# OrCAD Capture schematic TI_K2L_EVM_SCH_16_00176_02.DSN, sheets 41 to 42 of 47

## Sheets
41 PAGE27 : K2L_NAND FLASH&EEPROM: size C; title: K2L EMIF, VDD and VSSMON, EMIFWAIT1 bfr, NAND Flash, I2C EEPROM
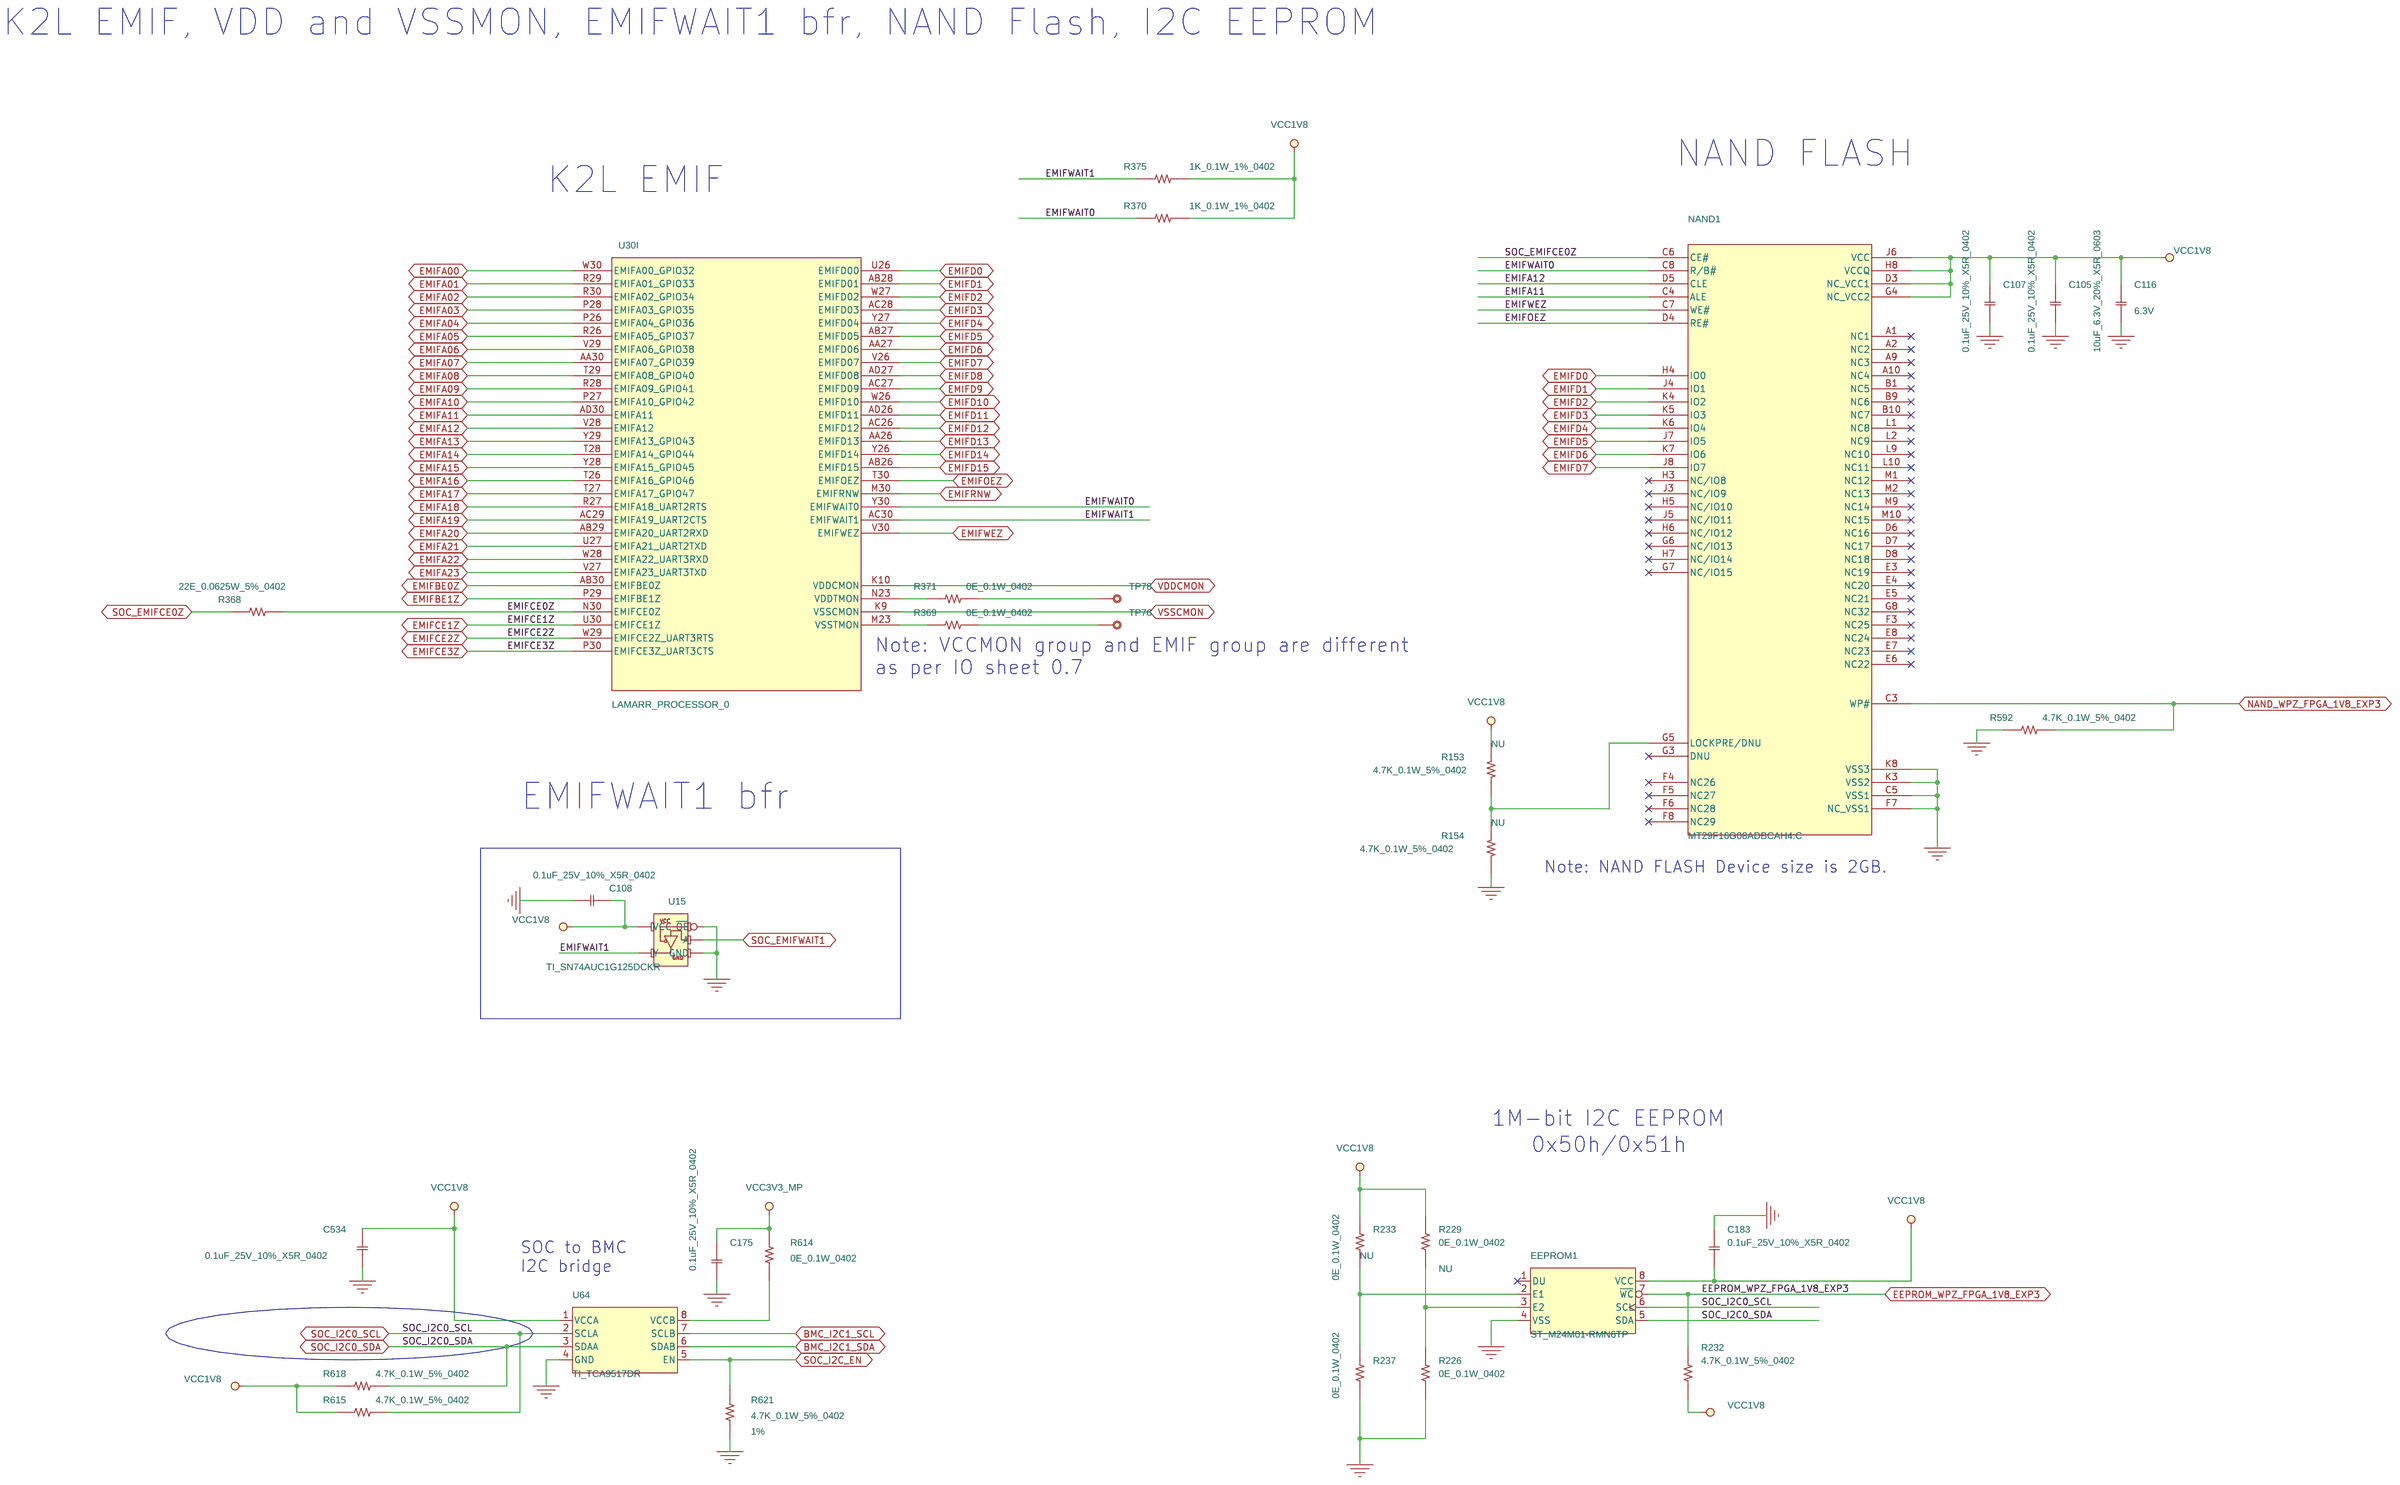
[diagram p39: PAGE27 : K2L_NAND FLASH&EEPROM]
42 PAGE41 : K2L_XDS200_EMULATION: size C; title: XDS200 Emulation CPLD
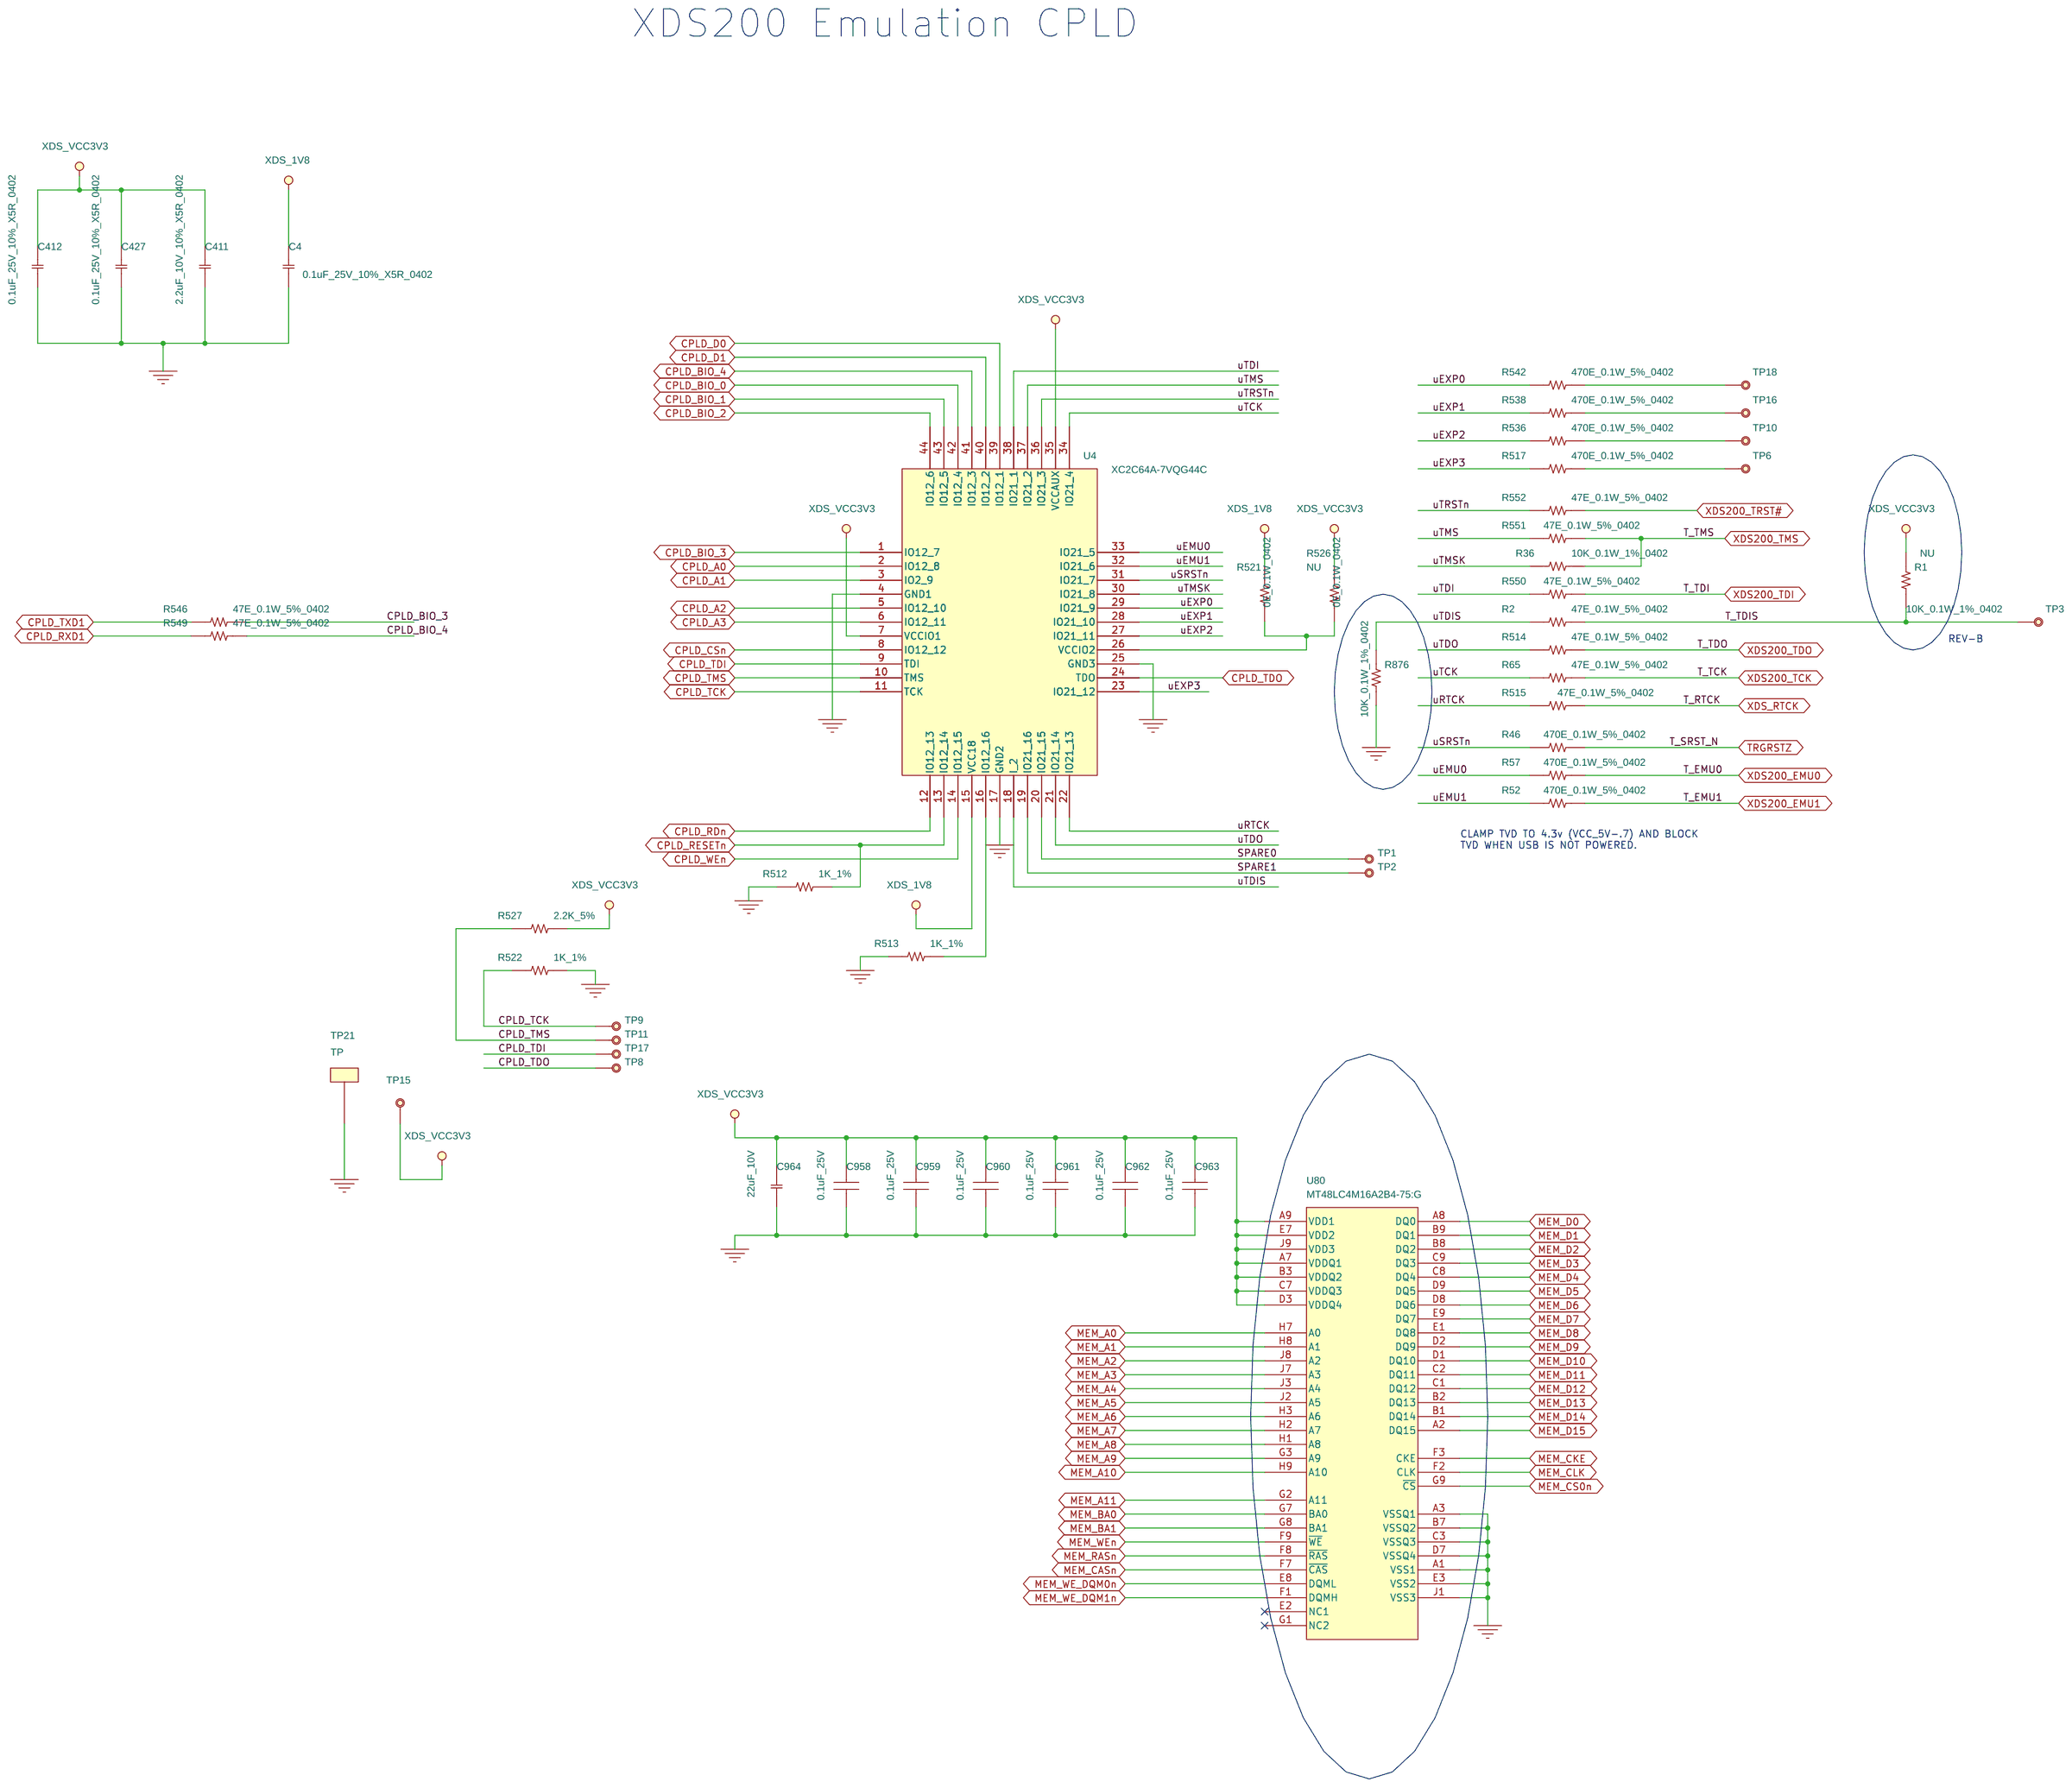
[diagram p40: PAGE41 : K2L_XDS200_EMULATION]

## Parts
sheet PAGE24 : K2L_JTAG
U30  LAMARR_PROCESSOR_0  [SKTBGA_Z3566_SS900-RHFB-BGA080]  (sections A,B,C,D,E,F,G,H,I,J,K,L,M,N,O,P,Q,R,S,T,U)
sheet PAGE27 : K2L_NAND FLASH&EEPROM
C105  0.1uF_25V_10%_X5R_0402  [C0402]
C107  0.1uF_25V_10%_X5R_0402  [C0402]
C108  0.1uF_25V_10%_X5R_0402  [C0402]
C116  10uF_6.3V_20%_X5R_0603  [C0603]
C175  0.1uF_25V_10%_X5R_0402  [C0402]
C183  0.1uF_25V_10%_X5R_0402  [C0402]
C534  0.1uF_25V_10%_X5R_0402  [C0402]
EEPROM1  ST_M24M01-RMN6TP  [SOIC_8P_50_193x236]
NAND1  MT29F16G08ADBCAH4:C  [BGA63C80P10X12_900X1100X100]
R153  4.7K_0.1W_5%_0402  [R0402]
R154  4.7K_0.1W_5%_0402  [R0402]
R226  0E_0.1W_0402  [R0402]
R229  0E_0.1W_0402  [R0402]
R232  4.7K_0.1W_5%_0402  [R0402]
R233  0E_0.1W_0402  [R0402]
R237  0E_0.1W_0402  [R0402]
R368  22E_0.0625W_5%_0402  [R0402]
R369  0E_0.1W_0402  [R0402]
R370  1K_0.1W_1%_0402  [R0402]
R371  0E_0.1W_0402  [R0402]
R375  1K_0.1W_1%_0402  [R0402]
R592  4.7K_0.1W_5%_0402  [R0402]
R614  0E_0.1W_0402  [R0402]
R615  4.7K_0.1W_5%_0402  [R0402]
R618  4.7K_0.1W_5%_0402  [R0402]
R621  4.7K_0.1W_5%_0402  [R0402]
TP76  TP  [TP-S40]
TP78  TP  [TP-S40]
U15  TI_SN74AUC1G125DCKR  [SC70_5P]
U64  TI_TCA9517DR  [SOIC_8P_50_193X236]
sheet PAGE41 : K2L_XDS200_EMULATION
C4  0.1uF_25V_10%_X5R_0402  [C0402]
C411  2.2uF_10V_10%_X5R_0402  [C0402]
C412  0.1uF_25V_10%_X5R_0402  [C0402]
C427  0.1uF_25V_10%_X5R_0402  [C0402]
C958  0.1uF_25V  [C0402]
C959  0.1uF_25V  [C0402]
C960  0.1uF_25V  [C0402]
C961  0.1uF_25V  [C0402]
C962  0.1uF_25V  [C0402]
C963  0.1uF_25V  [C0402]
C964  22uF_10V  [C0805]
R1  10K_0.1W_1%_0402  [R0402]
R2  47E_0.1W_5%_0402  [R0402]
R36  10K_0.1W_1%_0402  [R0402]
R46  470E_0.1W_5%_0402  [R0402]
R52  470E_0.1W_5%_0402  [R0402]
R57  470E_0.1W_5%_0402  [R0402]
R65  47E_0.1W_5%_0402  [R0402]
R512  1K_1%  [R0402]
R513  1K_1%  [R0402]
R514  47E_0.1W_5%_0402  [R0402]
R515  47E_0.1W_5%_0402  [R0402]
R517  470E_0.1W_5%_0402  [R0402]
R521  0E_0.1W_0402  [R0402]
R522  1K_1%  [R0402]
R526  0E_0.1W_0402  [R0402]
R527  2.2K_5%  [R0402]
R536  470E_0.1W_5%_0402  [R0402]
R538  470E_0.1W_5%_0402  [R0402]
R542  470E_0.1W_5%_0402  [R0402]
R546  47E_0.1W_5%_0402  [R0402]
R549  47E_0.1W_5%_0402  [R0402]
R550  47E_0.1W_5%_0402  [R0402]
R551  47E_0.1W_5%_0402  [R0402]
R552  47E_0.1W_5%_0402  [R0402]
R876  10K_0.1W_1%_0402  [R0402]
TP1  TP  [TP-S40]
TP2  TP  [TP-S40]
TP3  TP  [TP-S40]
TP6  TP  [TP-S40]
TP8  TP  [TP-S40]
TP9  TP  [TP-S40]
TP10  TP  [TP-S40]
TP11  TP  [TP-S40]
TP15  TP  [TP-S40]
TP16  TP  [TP-S40]
TP17  TP  [TP-S40]
TP18  TP  [TP-S40]
TP21  TP  [tp1-6040]
U4  XC2C64A-7VQG44C  [tqfp44]
U80  MT48LC4M16A2B4-75:G  [VFBGA54C80P9X9_800X800X100_EINF]

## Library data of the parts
U30 = LAMARR_PROCESSOR_7: LAMARR-SoC 900BGA 4DSP + 2ARM; Color: Default; Distributor_name: TBD; Distributor_part_number: TBD; EIC Part#: TBD; Location X-Coordinate: 0; Location Y-Coordinate: 0; Manufacture: TI; Manufacture Part Number: TCI6630K2L; Manufacture(English): TI; Manufacture_Part_Number: TCI6630K2L; Manufacturer: TI; Manufacturer_Part_No: TCI6630K2L; Mfg: TI; Mfg Part#: TBD; Mfr_name: TI; Mfr_part_number: LAMARR-SoC; Price @ 1: TBD; Price @ 10K: TBD; Price @ 1K: TBD; Primitive: DEFAULT; SPLIT_INST: TRUE; SWAP_INFO: (S1+S2+S3+S4+S5+S6+S7+S8+S9+S10+S11+S12+S13+S14+S15+S16+S17+S18+S19+S20+S21); Vendor: TBD; Vendor_Part_No: TBD; eI Part#: TBD
C105 C107 C108 C175 C183 C534 = 11_C_0: CAP CER 0.1UF 25V 10% X5R 0402; Avalue_Part_Number: E1123510400H; Distributor_name: DIGIKEY; Distributor_part_number: 445-4964-1-ND; EIC Part#: 03_00470_02; MOUNTED: <MOUNTED>; Manufacture: TDK Corporation; Manufacture Part Number: C1005X5R1E104K050BC; Manufacture(English): TDK Corporation; Manufacture_Part_Number: GRM155R71C104KA88D; Manufacturer: TDK Corporation; Manufacturer_Part_No: C1005X5R1E104K050BC; Mfg: Murata Electronics North America; Mfg Part#: 03_00470_02; Mfr_name: TDK Corporation; Mfr_part_number: C1005X5R1E104K050BC; Package: 0402; Price @ 1: 0.10000; Price @ 1K: 0.00420; ProcessType: SMT; Tolerance: 10%; Vendor: DIGIKEY; Vendor Part#: 445-4964-1-ND; Vendor_Part_No: 445-4964-1-ND; eI Part#: 03_00470_02
C116 = 11_C_0: CAP CER 10UF 6.3V 20% X5R 0603; Avalue_Part_Number: E1121610610H; Characteristic: 6.3V; Distributor_name: DIGIKEY; Distributor_part_number: 587-3383-1-ND; EIC Part#: 03_00605_01; GROUP: CPU1; Manufacture: Taiyo Yuden; Manufacture Part Number: JMK107ABJ106MAHT; Manufacture(English): Taiyo Yuden; Manufacture_Part_Number: JMK107ABJ106MAHT; Manufacturer: Taiyo Yuden; Manufacturer_Part_No: JMK107ABJ106MAHT; Mfg: Taiyo Yuden; Mfg Part#: JMK107ABJ106MAHT; Mfr_name: Taiyo Yuden; Mfr_part_number: JMK107ABJ106MAHT; Package: 0603; Part_Number: 1100004184; Price @ 1: 0.32000; Price @ 10K: 0.06105; Price @ 1K: 0.07755; ProcessType: SMT; ROOM: CPU1; Tolerance: 20%; Vendor: DIGIKEY; Vendor Part#: 587-3383-1-ND; Vendor_Part_No: 587-3383-1-ND; eI Part#: 03_00605_01
EEPROM1 = 141_ST_M24M01-HRMN6TP_0: IC EEPROM 1MBIT 1MHZ 8SO; AVL_Part: AVL; Distributor_name: DIGIKEY; Distributor_part_number: 497-6351-1-ND; EIC Part#: 01_01143_01; Manufacture: STMicroelectronics; Manufacture Part Number: M24M01-RMN6TP; Manufacture(English): STMicroelectronics; Manufacture_Part_Number: M24M01-RMN6TP; Manufacturer: STMicroelectronics; Manufacturer_Part_No: M24M01-RMN6TP; Mfg: STMicroelectronics; Mfg Part#: 01_01143_01; Mfr_name: STMicroelectronics; Mfr_part_number: M24M01-RMN6TP; Package: SOIC8; Part_Number: 1410021294-11; Price @ 1: 3.17000; Price @ 10K: 1.46300; Price @ 1K: 1.58400; ProcessType: SMT; Vendor: DIGIKEY; Vendor_Part_No: 497-6351-1-ND; eI Part#: 01_01143_01
NAND1 = IC_NAND_63VFBGA_MICRONx16: IC FLASH 16G SLC VFBGA; Distributor_name: TBD; Distributor_part_number: TBD; EIC Part#: 01_01145_01; Manufacture: Micron; Manufacture(English): Micron; Manufacturer: Micron; Mfg Part#: 01_01145_01; Mfr_name: Micron; Vendor: TBD; Vendor_Part_No: TBD; eI Part#: 01_01145_01
R153 R154 = 10_R_0: RES 4.7K OHM 1/10W 5% 0402 SMD; Advansus_Part_Number: 10G212472004030; Avalue_Part_Number: E1050704720H; Characteristic: 5%; Distributor_name: DIGIKEY; Distributor_part_number: P4.7KJCT-ND; EIC Part#: 02_00023_01; MOUNTED: <MOUNTED>; Manufacture: Panasonic - ECG; Manufacture Part Number: ERJ-2GEJ472X; Manufacture(English): Panasonic - ECG; Manufacture_Part_Number: ERJ-2GEJ472X; Manufacturer: Panasonic - ECG; Manufacturer_Part_No: ERJ-2GEJ472X; Mfg: Panasonic Electronic Components; Mfg Part#: 02_00266_01; Mfr_name: Panasonic - ECG; Mfr_part_number: ERJ-2GEJ472X; Mounting Status: NU; Mounting_Status: NU; Package: 0402; Part_Number: 105A747014; Price @ 1: 0.10000; Price @ 10K: 0.00347; Price @ 1K: 0.00672; ProcessType: SMT; Tolerance: 5%; Vendor: DIGIKEY; Vendor_Part_No: P4.7KJCT-ND; eI Part#: 02_00023_01
R226 R237 R614 = 10_R_0: RES 0.0 OHM 1/10W JUMP 0402 SMD; Characteristic: 5%; Distributor_name: DIGIKEY; Distributor_part_number: P0.0JCT-ND; EIC Part#: 02_00019_01; MOUNTED: <MOUNTED>; Manufacture: Panasonic - ECG; Manufacture Part Number: ERJ-2GE0R00X; Manufacture(English): Panasonic - ECG; Manufacture_Part_Number: ERJ-2GE0R00X; Manufacturer: Panasonic - ECG; Manufacturer_Part_No: ERJ-2GE0R00X; Mfg: Panasonic Electronic Components; Mfg Part#: 02_00019_01; Mfr_name: Panasonic - ECG; Mfr_part_number: ERJ-2GE0R00X; Package: 0402; Part_Number: 105A700004; Price @ 1: 0.05000; Price @ 10K: 0.00248; Price @ 1K: 0.00480; ProcessType: SMT; Tolerance: 5%; Vendor: DIGIKEY; Vendor_Part_No: P0.0JCT-ND; eI Part#: 02_00019_01
R229 R233 = 10_R_0: RES 0.0 OHM 1/10W JUMP 0402 SMD; Characteristic: 5%; Distributor_name: DIGIKEY; Distributor_part_number: P0.0JCT-ND; EIC Part#: 02_00019_01; MOUNTED: NU; Manufacture: Panasonic - ECG; Manufacture Part Number: ERJ-2GE0R00X; Manufacture(English): Panasonic - ECG; Manufacture_Part_Number: ERJ-2GE0R00X; Manufacturer: Panasonic - ECG; Manufacturer_Part_No: ERJ-2GE0R00X; Mfg: Panasonic Electronic Components; Mfg Part#: 02_00019_01; Mfr_name: Panasonic - ECG; Mfr_part_number: ERJ-2GE0R00X; Mounting Status: NU; Mounting_Status: NU; Package: 0402; Part_Number: 105A700004; Price @ 1: 0.05000; Price @ 10K: 0.00248; Price @ 1K: 0.00480; ProcessType: SMT; Tolerance: 5%; Vendor: DIGIKEY; Vendor_Part_No: P0.0JCT-ND; eI Part#: 02_00019_01
R232 R592 = 10_R_0: RES 4.7K OHM 1/10W 5% 0402 SMD; Advansus_Part_Number: 10G212472004030; Avalue_Part_Number: E1050704720H; Characteristic: 5%; Distributor_name: DIGIKEY; Distributor_part_number: P4.7KJCT-ND; EIC Part#: 02_00023_01; MOUNTED: <MOUNTED>; Manufacture: Panasonic - ECG; Manufacture Part Number: ERJ-2GEJ472X; Manufacture(English): Panasonic - ECG; Manufacture_Part_Number: ERJ-2GEJ472X; Manufacturer: Panasonic - ECG; Manufacturer_Part_No: ERJ-2GEJ472X; Mfg: Panasonic Electronic Components; Mfg Part#: 02_00266_01; Mfr_name: Panasonic - ECG; Mfr_part_number: ERJ-2GEJ472X; Package: 0402; Part_Number: 105A747014; Price @ 1: 0.10000; Price @ 10K: 0.00347; Price @ 1K: 0.00672; ProcessType: SMT; Tolerance: 5%; Vendor: DIGIKEY; Vendor_Part_No: P4.7KJCT-ND; eI Part#: 02_00023_01
R368 = 10_R_0: RES 22 OHM 1/16W 1% 0402 SMD; Characteristic: 5%; Distributor_name: DIGIKEY; Distributor_part_number: P22JCT-ND; EIC Part#: 02_00233_01; MOUNTED: <MOUNTED>; Manufacture: Panasonic - ECG; Manufacture Part Number: ERJ-2GEJ220X; Manufacture(English): Panasonic - ECG; Manufacture_Part_Number: ERJ-2GEJ220X; Manufacturer: Panasonic - ECG; Manufacturer_Part_No: ERJ-2GEJ220X; Mfg: Panasonic - ECG; Mfg Part#: ERJ-2GEJ220X; Mfr_name: Panasonic - ECG; Mfr_part_number: ERJ-2GEJ220X; Package: 0402; Part_Number: 105A722064; Price @ 1: 0.10000; Price @ 10K: 0.00132; Price @ 1K: 0.00233; ProcessType: SMT; Tolerance: 5%; Vendor: DIGIKEY; Vendor Part#: P22JCT-ND; Vendor_Part_No: P22JCT-ND; eI Part#: 02_00233_01
R369 R371 = 10_R_0: RES 0.0 OHM 1/10W JUMP 0402 SMD; Characteristic: 5%; Distributor_name: DIGIKEY; Distributor_part_number: P0.0JCT-ND; EIC Part#: 02_00019_01; Manufacture: Panasonic - ECG; Manufacture Part Number: ERJ-2GE0R00X; Manufacture(English): Panasonic - ECG; Manufacture_Part_Number: ERJ-2GE0R00X; Manufacturer: Panasonic - ECG; Manufacturer_Part_No: ERJ-2GE0R00X; Mfg: Panasonic Electronic Components; Mfg Part#: 02_00019_01; Mfr_name: Panasonic - ECG; Mfr_part_number: ERJ-2GE0R00X; Package: 0402; Part_Number: 105A700004; Price @ 1: 0.05000; Price @ 10K: 0.00248; Price @ 1K: 0.00480; ProcessType: SMT; Tolerance: 5%; Vendor: DIGIKEY; Vendor_Part_No: P0.0JCT-ND; eI Part#: 02_00019_01
R370 R375 = 10_R_0: RES 1.00K OHM 1/10W 1% 0402 SMD; Characteristic: 1%; Distributor_name: DIGIKEY; Distributor_part_number: P1.00KLCT-ND; EIC Part#: 02_00045_01; MOUNTED: <MOUNTED>; Manufacture: Panasonic - ECG; Manufacture Part Number: ERJ-2RKF1001X; Manufacture(English): Panasonic - ECG; Manufacture_Part_Number: ERJ-2RKF1001X; Manufacturer: Panasonic - ECG; Manufacturer_Part_No: ERJ-2RKF1001X; Mfg: Panasonic Electronic Components; Mfg Part#: 02_00045_01; Mfr_name: Panasonic - ECG; Mfr_part_number: ERJ-2RKF1001X; Package: 0402; Part_Number: 105A510014; Price @ 1: 0.10000; Price @ 10K: 0.00347; Price @ 1K: 0.00672; ProcessType: SMT; Tolerance: 1%; Vendor: DIGIKEY; Vendor_Part_No: P1.00KLCT-ND; eI Part#: 02_00045_01
R615 R618 R621 = 10_R_0: RES 4.7K OHM 1/10W 5% 0402 SMD; AVL_Part: AVL; Advansus_Part_Number: 10G212470114030; Characteristic: 1%; Distributor_name: DIGIKEY; Distributor_part_number: P4.7KJCT-ND; EIC Part#: 02_00023_01; MOUNTED: <MOUNTED>; Manufacture: Panasonic - ECG; Manufacture Part Number: ERJ-2GEJ472X; Manufacture(English): Panasonic - ECG; Manufacture_Part_Number: ERJ-2GEJ472X; Manufacturer: Panasonic - ECG; Manufacturer_Part_No: ERJ-2GEJ472X; Mfg: Panasonic Electronic Components; Mfg Part#: 02_00266_01; Mfr_name: Panasonic - ECG; Mfr_part_number: ERJ-2GEJ472X; Package: 0402; Part_Number: 1000000558-04; Price @ 1: 0.10000; Price @ 10K: 0.00347; Price @ 1K: 0.00672; ProcessType: SMT; Tolerance: 1%; Vendor: DIGIKEY; Vendor_Part_No: P4.7KJCT-ND; eI Part#: 02_00023_01
TP76 TP78 = 00_TP28_0: TEST PAD TP; Advansus_Part_Number: 0030000003; Avalue_Part_Number: 0030000003; Distributor_name: NA; Distributor_part_number: NA; EIC Part#: NA; Manufacture: NA; Manufacture Part Number: NA; Manufacture(English): NA; Manufacture_Part_Number: NA; Manufacturer: NA; Manufacturer_Part_No: NA; Mfg: NA; Mfg Part#: NA; Mfr_name: NA; Mfr_part_number: NA; Part_Number: 0030000003; Price @ 1: NA; Price @ 10K: NA; Price @ 1K: NA; ProcessType: SMT; Vendor: NA; Vendor_Part_No: NA; eI Part#: NA
U15 = 141_TI_SN74AUC1G125DCKR_0: IC BUS BUFF TRI-ST N-INV SC705; AVL_Part: AVL; Advansus_Part_Number: 06GA1410009148; Distributor_name: DIGIKEY; Distributor_part_number: 296-12658-1-ND; EIC Part#: TBD; Manufacture: TI; Manufacture Part Number: SN74AUC1G125DCKR; Manufacture(English): TI; Manufacture_Part_Number: SN74AUC1G125DCKR; Manufacturer: TI; Manufacturer_Part_No: SN74AUC1G125DCKR; Mfg: TI; Mfg Part#: TBD; Mfr_name: TI; Mfr_part_number: SN74AUC1G125DCKR; Package: SC70-5; Part_Number: 1410009148; Price @ 1: 0.57000; Price @ 10K: 0.10440; Price @ 1K: 0.11948; ProcessType: SMT; Tolerance: NA; Vendor: DIGIKEY; Vendor_Part_No: 296-12658-1-ND; eI Part#: 01_00039_01
U64 = 141_TI_PCA9517DR_0: IC LVL-TRANSL I2C BUS REP 8-SOIC; AVL_Part: AVL; Alternate_Mfr: TI; Alternate_Partno: TCA9517DR; Distributor_name: DIGIKEY; Distributor_part_number: 296-23734-1-ND; EIC Part#: TBD; Manufacture: TI; Manufacture Part Number: PCA9517DR; Manufacture(English): TI; Manufacture_Part_Number: PCA9517DR; Manufacturer: TI; Manufacturer_Part_No: PCA9517DR; Mfg: TI; Mfg Part#: TBD; Mfr_name: TI; Mfr_part_number: PCA9517DR; Package: SOIC8; Part_Number: 1410015122; Price @ 1: 2.94000; Price @ 10K: 1.35660; Price @ 1K: 1.46880; ProcessType: SMT; Vendor: DIGIKEY; Vendor_Part_No: 296-23734-1-ND; eI Part#: 01_00472_01
C4 C412 C427 = 11_C_0: CAP CER 0.1UF 25V 10% X5R 0402; Alt Mfg: Taiyo Yuden; Distributor_name: DIGIKEY; Distributor_part_number: 445-4964-1-ND; EIC Part#: 03_00470_02; Manufacture: TDK Corporation; Manufacture Part Number: C1005X5R1E104K050BC; Manufacture(English): TDK Corporation; Manufacture_Part_Number: GRM155R61E104KA87D; Manufacturer: TDK Corporation; Manufacturer_Part_No: C1005X5R1E104K050BC; Mfg: Murata Electronics North America; Mfg Part#: 03_00470_02; Mfr_name: TDK Corporation; Mfr_part_number: C1005X5R1E104K050BC; Oper. Temp. Range: -55°C ~ 85°C; Package: 0402; Price @ 1: 0.10000; Price @ 1K: 0.00960; ProcessType: SMT; RoHS: Yes; Tolerance: 10%; Vendor: DIGIKEY; Vendor Part#: 445-4964-1-ND; Vendor_Part_No: 445-4964-1-ND; eI Part#: 03_00470_02
C411 = 11_C_0: CAP CER 2.2UF 10V 10% X5R 0402; AVL_Part: AVL; Advansus_Part_Number: 11G233222516360; Characteristic: 10V; Distributor_name: DIGIKEY; Distributor_part_number: 445-7392-1-ND; EIC Part#: 03_00055_05; Manufacture: TDK Corporation; Manufacture Part Number: C1005X5R1A225K050BC; Manufacture(English): TDK Corporation; Manufacture_Part_Number: C1005X5R1A225K050BC; Manufacturer: TDK Corporation; Manufacturer_Part_No: C1005X5R1A225K050BC; Mfg: TDK Corporation; Mfg Part#: C1005X5R1A225K050BC; Mfr_name: TDK Corporation; Mfr_part_number: C1005X5R1A225K050BC; Package: 0402; Part_Number: 1100007233-01; Price @ 1: 0.13000; Price @ 10K: 0.01935; Price @ 1K: 0.02475; ProcessType: SMT; Tolerance: 10%; Vendor: DIGIKEY; Vendor_Part_No: 445-7392-1-ND; eI Part#: 03_00055_05
C958-C963 = CAP: CAP CER 0.1UF 25V 10% X5R 0402; Distributor_name: DIGIKEY; Distributor_part_number: 445-4964-1-ND; EIC Part#: 03_00470_02; Manufacture: TDK Corporation; Manufacture Part Number: C1005X5R1E104K050BC; Manufacture(English): TDK Corporation; Manufacture_Part_Number: GRM155R61E104KA87D; Manufacturer: TDK Corporation; Manufacturer_Part_No: C1005X5R1E104K050BC; Mfg: Murata Electronics North America; Mfg Part#: 03_00470_02; Mfr_name: TDK Corporation; Mfr_part_number: C1005X5R1E104K050BC; Price @ 1: 0.10000; Price @ 1K: 0.00960; Vendor: DIGIKEY; Vendor Part#: 445-4964-1-ND; Vendor_Part_No: 445-4964-1-ND; eI Part#: 03_00470_02
C964 = 11_C_0: CAP CER 22UF 10V 20% X5R 0805; Characteristic: 6.3V; Distributor_name: DIGIKEY; Distributor_part_number: 587-1958-1-ND; EIC Part#: 03_00263_01; Manufacture: Taiyo Yuden; Manufacture Part Number: LMK212BJ226MG-T; Manufacture(English): Taiyo Yuden; Manufacture_Part_Number: LMK212BJ226MG-T; Manufacturer: Taiyo Yuden; Manufacturer_Part_No: LMK212BJ226MG-T; Mfg: Taiyo Yuden; Mfg Part#: 03_00263_01; Mfr_name: Taiyo Yuden; Mfr_part_number: LMK212BJ226MG-T; Package: 0805; Part_Number: 1100000254; Price @ 1: 0.53000; Price @ 10K: 0.12000; Price @ 1K: 0.16875; ProcessType: SMT; Tolerance: 20%; Vendor: DIGIKEY; Vendor Part#: 587-1958-1-ND; Vendor_Part_No: 587-1958-1-ND; eI Part#: 03_00263_01
R1 = 10_R_0: RES 10K OHM 1/10W 1% 0402 SMD; Alt Mfg: Yageo; Alt Mfg Part#: RC0402FR-0710KL; Distributor_name: DIGIKEY; Distributor_part_number: P10.0KLCT-ND; EIC Part#: 02_00027_01; Manufacture: Panasonic - ECG; Manufacture Part Number: ERJ-2RKF1002X; Manufacture(English): Panasonic - ECG; Manufacture_Part_Number: ERJ-2RKF1002X; Manufacturer: Panasonic - ECG; Manufacturer_Part_No: ERJ-2RKF1002X; Mfg Part#: 02_00027_01; Mfr_name: Panasonic - ECG; Mfr_part_number: ERJ-2RKF1002X; Mounting: NU; Mounting Status: NU; Mounting_Status: NU; Oper. Temp. Range: -55C ~ 125C; Package: 0402; Price @ 1: 0.10000; Price @ 10K: 0.00347; Price @ 1K: 0.00672; ProcessType: SMT; Remark: Alt part is 1/16W; RoHS: Yes; Tolerance: 1%; Vendor: DIGIKEY; Vendor Part#: P10.0KLCT-ND; Vendor_Part_No: P10.0KLCT-ND; eI Part#: 02_00027_01
R2 = 10_R_0: RES 47 OHM 1/10W 5% 0402 SMD; Alt Mfg: Yageo; Alt Mfg Part#: RC0402JR-070RL; Distributor_name: DIGIKEY; Distributor_part_number: P47JCT-ND; EIC Part#: 02_00558_01; Manufacture: Panasonic - ECG; Manufacture Part Number: ERJ-2GEJ470X; Manufacture(English): Panasonic - ECG; Manufacture_Part_Number: ERJ-2GEJ470X; Manufacturer: Panasonic - ECG; Manufacturer_Part_No: ERJ-2GEJ470X; Mfg Part#: 02_00558_01; Mfr_name: Panasonic - ECG; Mfr_part_number: ERJ-2GEJ470X; Oper. Temp. Range: -55C to 125C; Package: 0402; ProcessType: SMT; Remark: Alt part is 1/16W; RoHS: Yes; Tolerance: 5%; Vendor: DIGIKEY; Vendor Part#: P47JCT-ND; Vendor_Part_No: P47JCT-ND; eI Part#: 02_00043_02
R36 R876 = 10_R_0: RES 10K OHM 1/10W 1% 0402 SMD; Alt Mfg: Yageo; Alt Mfg Part#: RC0402FR-0710KL; Distributor_name: DIGIKEY; Distributor_part_number: P10.0KLCT-ND; EIC Part#: 02_00027_01; Manufacture: Panasonic - ECG; Manufacture Part Number: ERJ-2RKF1002X; Manufacture(English): Panasonic - ECG; Manufacture_Part_Number: ERJ-2RKF1002X; Manufacturer: Panasonic - ECG; Manufacturer_Part_No: ERJ-2RKF1002X; Mfg Part#: 02_00027_01; Mfr_name: Panasonic - ECG; Mfr_part_number: ERJ-2RKF1002X; Oper. Temp. Range: -55C ~ 125C; Package: 0402; Price @ 1: 0.10000; Price @ 10K: 0.00347; Price @ 1K: 0.00672; ProcessType: SMT; Remark: Alt part is 1/16W; RoHS: Yes; Tolerance: 1%; Vendor: DIGIKEY; Vendor Part#: P10.0KLCT-ND; Vendor_Part_No: P10.0KLCT-ND; eI Part#: 02_00027_01
R46 R57 = 10_R_0: RES 470 OHM 1/10W 5% 0402 SMD; Alt Mfg: Yageo; Alt Mfg Part#: RC0402JR-070RL; Distributor_name: DIGIKEY; Distributor_part_number: P470JCT-ND; EIC Part#: 02_00483_01; Manufacture: Panasonic - ECG; Manufacture Part Number: ERJ-2GEJ471X; Manufacture(English): Panasonic - ECG; Manufacture_Part_Number: ERJ-2GEJ471X; Manufacturer: Panasonic - ECG; Manufacturer_Part_No: ERJ-2GEJ471X; Mfg Part#: 02_00483_01; Mfr_name: Panasonic - ECG; Mfr_part_number: ERJ-2GEJ471X; Oper. Temp. Range: -55C to 125C; Package: 0402; ProcessType: SMT; Remark: Alt part is 1/16W; RoHS: Yes; Tolerance: 5%; Vendor: DIGIKEY; Vendor Part#: P470JDKR-ND; Vendor_Part_No: P470JCT-ND; eI Part#: 02_00972_01
R52 R542 = 10_R_0: RES 470 OHM 1/10W 5% 0402 SMD; Alt Mfg: Yageo; Alt Mfg Part#: RC0402JR-070RL; Distributor_name: DIGIKEY; Distributor_part_number: P470JCT-ND; EIC Part#: 02_00483_01; Manufacture: Panasonic - ECG; Manufacture Part Number: ERJ-2GEJ471X; Manufacture(English): Panasonic - ECG; Manufacture_Part_Number: ERJ-2GEJ471X; Manufacturer: Panasonic - ECG; Manufacturer_Part_No: ERJ-2GEJ471X; Mfg Part#: 02_00483_01; Mfr_name: Panasonic - ECG; Mfr_part_number: ERJ-2GEJ471X; Oper. Temp. Range: -55C to 125C; Package: 0402; ProcessType: SMT; Remark: Alt part is 1/16W; RoHS: Yes; Tolerance: 5%; Vendor: DIGIKEY; Vendor Part#: P470JDKR-ND; Vendor_Part_No: P470JCT-ND; eI Part#: TBD
R65 R515 R546 R550 = 10_R_0: RES 47 OHM 1/10W 5% 0402 SMD; Alt Mfg: Yageo; Alt Mfg Part#: RC0402JR-070RL; Distributor_name: DIGIKEY; Distributor_part_number: P47JCT-ND; EIC Part#: 02_00558_01; Manufacture: Panasonic - ECG; Manufacture Part Number: ERJ-2GEJ470X; Manufacture(English): Panasonic - ECG; Manufacture_Part_Number: ERJ-2GEJ470X; Manufacturer: Panasonic - ECG; Manufacturer_Part_No: ERJ-2GEJ470X; Mfg Part#: 02_00558_01; Mfr_name: Panasonic - ECG; Mfr_part_number: ERJ-2GEJ470X; Oper. Temp. Range: -55C to 125C; Package: 0402; ProcessType: SMT; Remark: Alt part is 1/16W; RoHS: Yes; Tolerance: 5%; Vendor: DIGIKEY; Vendor Part#: P47JCT-ND; Vendor_Part_No: P47JCT-ND; eI Part#: 02_00019_01
R512 R513 R522 = 10_R_0: RES 1.00K OHM 1/10W 1% 0402 SMD; Alt Mfg: Yageo; Distributor_name: DIGIKEY; Distributor_part_number: P1.00KLCT-ND; EIC Part#: 02_00045_01; MOUNTED: <MOUNTED>; Manufacture: Panasonic - ECG; Manufacture Part Number: ERJ-2RKF1001X; Manufacture(English): Panasonic - ECG; Manufacture_Part_Number: ERJ-2RKF1001X; Manufacturer: Panasonic - ECG; Manufacturer_Part_No: ERJ-2RKF1001X; Mfg Part#: 02_00045_01; Mfr_name: Panasonic - ECG; Mfr_part_number: ERJ-2RKF1001X; Oper. Temp. Range: -55C to 125C; Package: 0402; ProcessType: SMT; RoHS: Yes; Tolerance: 1%; Vendor: DIGIKEY; Vendor Part#: P1.00KLCT-ND; Vendor_Part_No: P1.00KLCT-ND; eI Part#: 02_00045_01
R514 R549 = 10_R_0: RES 47 OHM 1/10W 5% 0402 SMD; Alt Mfg: Yageo; Alt Mfg Part#: RC0402JR-070RL; Distributor_name: DIGIKEY; Distributor_part_number: P47JCT-ND; EIC Part#: 02_00558_01; Manufacture: Panasonic - ECG; Manufacture Part Number: ERJ-2GEJ470X; Manufacture(English): Panasonic - ECG; Manufacture_Part_Number: ERJ-2GEJ470X; Manufacturer: Panasonic - ECG; Manufacturer_Part_No: ERJ-2GEJ470X; Mfg Part#: 02_00558_01; Mfr_name: Panasonic - ECG; Mfr_part_number: ERJ-2GEJ470X; Oper. Temp. Range: -55C to 125C; Package: 0402; ProcessType: SMT; Remark: Alt part is 1/16W; RoHS: Yes; Tolerance: 5%; Vendor: DIGIKEY; Vendor Part#: P47JCT-ND; Vendor_Part_No: P47JCT-ND; eI Part#: 02_00233_01
R517 = 10_R_0: RES 470 OHM 1/10W 5% 0402 SMD; Alt Mfg: Yageo; Alt Mfg Part#: RC0402JR-070RL; Distributor_name: DIGIKEY; Distributor_part_number: P470JCT-ND; EIC Part#: 02_00483_01; Manufacture: Panasonic - ECG; Manufacture Part Number: ERJ-2GEJ471X; Manufacture(English): Panasonic - ECG; Manufacture_Part_Number: ERJ-2GEJ471X; Manufacturer: Panasonic - ECG; Manufacturer_Part_No: ERJ-2GEJ471X; Mfg Part#: 02_00483_01; Mfr_name: Panasonic - ECG; Mfr_part_number: ERJ-2GEJ471X; Oper. Temp. Range: -55C to 125C; Package: 0402; ProcessType: SMT; Remark: Alt part is 1/16W; RoHS: Yes; Tolerance: 5%; Vendor: DIGIKEY; Vendor Part#: P470JDKR-ND; Vendor_Part_No: P470JCT-ND; eI Part#: 02_00027_01
R521 = 10_R_0: RES 0.0 OHM 1/10W JUMP 0402 SMD; Alt Mfg: Yageo; Distributor_name: DIGIKEY; Distributor_part_number: P0.0JCT-ND; EIC Part#: 02_00019_01; Manufacture: Panasonic - ECG; Manufacture Part Number: ERJ-2GE0R00X; Manufacture(English): Panasonic - ECG; Manufacture_Part_Number: ERJ-2GE0R00X; Manufacturer: Panasonic - ECG; Manufacturer_Part_No: ERJ-2GE0R00X; Mfg Part#: 02_00019_01; Mfr_name: Panasonic - ECG; Mfr_part_number: ERJ-2GE0R00X; Oper. Temp. Range: -55C to 125C; Package: 0402; ProcessType: SMT; Remark: Alt part is 1/16W; RoHS: Yes; Tolerance: 5%; Vendor: DIGIKEY; Vendor Part#: P0.0JCT-ND; Vendor_Part_No: P0.0JCT-ND; eI Part#: 02_00019_01
R526 = 10_R_0: RES 0.0 OHM 1/10W JUMP 0402 SMD; Alt Mfg: Yageo; Distributor_name: DIGIKEY; Distributor_part_number: P0.0JCT-ND; EIC Part#: 02_00019_01; Manufacture: Panasonic - ECG; Manufacture Part Number: ERJ-2GE0R00X; Manufacture(English): Panasonic - ECG; Manufacture_Part_Number: ERJ-2GE0R00X; Manufacturer: Panasonic - ECG; Manufacturer_Part_No: ERJ-2GE0R00X; Mfg Part#: 02_00019_01; Mfr_name: Panasonic - ECG; Mfr_part_number: ERJ-2GE0R00X; Mounting: NU; Mounting Status: NU; Mounting_Status: NU; Oper. Temp. Range: -55C to 125C; Package: 0402; ProcessType: SMT; Remark: Alt part is 1/16W; RoHS: Yes; Tolerance: 5%; Vendor: DIGIKEY; Vendor Part#: P0.0JCT-ND; Vendor_Part_No: P0.0JCT-ND; eI Part#: 02_00019_01
R527 = 10_R_0: RES 2.2K OHM 1/10W 5% 0402 SMD; Alt Mfg: Yageo; Alt Mfg Part#: RC0402JR-072K2L; Distributor_name: DIGIKEY; Distributor_part_number: P2.2KJCT-ND; EIC Part#: 02_00024_01; Manufacture: Panasonic - ECG; Manufacture Part Number: ERJ-2GEJ222X; Manufacture(English): Panasonic - ECG; Manufacture_Part_Number: ERJ-2GEJ222X; Manufacturer: Panasonic - ECG; Manufacturer_Part_No: ERJ-2GEJ222X; Mfg Part#: 02_00024_01; Mfr_name: Panasonic - ECG; Mfr_part_number: ERJ-2GEJ222X; Oper. Temp. Range: -55C to 125C; Package: 0402; ProcessType: SMT; Remark: Alt part is 1/16W; RoHS: Yes; Specifications: RES 2.2K OHM 1/10W 5% 0402 SMD; Tolerance: 5%; Vendor: DIGIKEY; Vendor Part#: P2.2KJCT-ND; Vendor_Part_No: P2.2KJCT-ND; eI Part#: 09_00060_01
R536 = 10_R_0: RES 470 OHM 1/10W 5% 0402 SMD; Alt Mfg: Yageo; Alt Mfg Part#: RC0402JR-070RL; Distributor_name: DIGIKEY; Distributor_part_number: P470JCT-ND; EIC Part#: 02_00483_01; Manufacture: Panasonic - ECG; Manufacture Part Number: ERJ-2GEJ471X; Manufacture(English): Panasonic - ECG; Manufacture_Part_Number: ERJ-2GEJ471X; Manufacturer: Panasonic - ECG; Manufacturer_Part_No: ERJ-2GEJ471X; Mfg Part#: 02_00483_01; Mfr_name: Panasonic - ECG; Mfr_part_number: ERJ-2GEJ471X; Oper. Temp. Range: -55C to 125C; Package: 0402; ProcessType: SMT; Remark: Alt part is 1/16W; RoHS: Yes; Tolerance: 5%; Vendor: DIGIKEY; Vendor Part#: P470JDKR-ND; Vendor_Part_No: P470JCT-ND; eI Part#: 02_00200_04
R538 = 10_R_0: RES 470 OHM 1/10W 5% 0402 SMD; Alt Mfg: Yageo; Alt Mfg Part#: RC0402JR-070RL; Distributor_name: DIGIKEY; Distributor_part_number: P470JCT-ND; EIC Part#: 02_00483_01; Manufacture: Panasonic - ECG; Manufacture Part Number: ERJ-2GEJ471X; Manufacture(English): Panasonic - ECG; Manufacture_Part_Number: ERJ-2GEJ471X; Manufacturer: Panasonic - ECG; Manufacturer_Part_No: ERJ-2GEJ471X; Mfg Part#: 02_00483_01; Mfr_name: Panasonic - ECG; Mfr_part_number: ERJ-2GEJ471X; Oper. Temp. Range: -55C to 125C; Package: 0402; ProcessType: SMT; Remark: Alt part is 1/16W; RoHS: Yes; Tolerance: 5%; Vendor: DIGIKEY; Vendor Part#: P470JDKR-ND; Vendor_Part_No: P470JCT-ND; eI Part#: 02_00961_01
R551 = 10_R_0: RES 47 OHM 1/10W 5% 0402 SMD; Alt Mfg: Yageo; Alt Mfg Part#: RC0402JR-070RL; Distributor_name: DIGIKEY; Distributor_part_number: P47JCT-ND; EIC Part#: 02_00558_01; Manufacture: Panasonic - ECG; Manufacture Part Number: ERJ-2GEJ470X; Manufacture(English): Panasonic - ECG; Manufacture_Part_Number: ERJ-2GEJ470X; Manufacturer: Panasonic - ECG; Manufacturer_Part_No: ERJ-2GEJ470X; Mfg Part#: 02_00558_01; Mfr_name: Panasonic - ECG; Mfr_part_number: ERJ-2GEJ470X; Oper. Temp. Range: -55C to 125C; Package: 0402; ProcessType: SMT; Remark: Alt part is 1/16W; RoHS: Yes; Tolerance: 5%; Vendor: DIGIKEY; Vendor Part#: P47JCT-ND; Vendor_Part_No: P47JCT-ND; eI Part#: 02_00027_01
R552 = 10_R_0: RES 47 OHM 1/10W 5% 0402 SMD; Alt Mfg: Yageo; Alt Mfg Part#: RC0402JR-070RL; Distributor_name: DIGIKEY; Distributor_part_number: P47JCT-ND; EIC Part#: 02_00558_01; Manufacture: Panasonic - ECG; Manufacture Part Number: ERJ-2GEJ470X; Manufacture(English): Panasonic - ECG; Manufacture_Part_Number: ERJ-2GEJ470X; Manufacturer: Panasonic - ECG; Manufacturer_Part_No: ERJ-2GEJ470X; Mfg Part#: 02_00558_01; Mfr_name: Panasonic - ECG; Mfr_part_number: ERJ-2GEJ470X; Oper. Temp. Range: -55C to 125C; Package: 0402; ProcessType: SMT; Remark: Alt part is 1/16W; RoHS: Yes; Tolerance: 5%; Vendor: DIGIKEY; Vendor Part#: P47JCT-ND; Vendor_Part_No: P47JCT-ND; eI Part#: 02_00045_01
TP1-TP3 TP6 TP8-TP11 TP15-TP18 = 00_TP-S40_0: TEST PAD TP; Distributor_name: NA; Distributor_part_number: NA; EIC Part#: NA; Manufacture: NA; Manufacture Part Number: NA; Manufacture(English): NA; Manufacture_Part_Number: NA; Manufacturer: NA; Manufacturer_Part_No: NA; Mfg: NA; Mfg Part#: NA; Mfr_name: NA; Mfr_part_number: NA; Oper. Temp. Range: --NA--; Package: --NA--; Price @ 1: NA; Price @ 10K: NA; Price @ 1K: NA; ProcessType: SMT; RoHS: Yes; Vendor: NA; Vendor Part#: --NA--; Vendor_Part_No: NA; eI Part#: NA
TP21 = TEST_POINT: TEST PAD TP; Distributor_name: NA; Distributor_part_number: NA; EIC Part#: NA; Manufacture: NA; Manufacture Part Number: NA; Manufacture(English): NA; Manufacture_Part_Number: NA; Manufacturer: NA; Manufacturer_Part_No: NA; Mfg: NA; Mfg Part#: NA; Mfr_name: NA; Mfr_part_number: NA; Part #: 100115-0001R; Price @ 1: NA; Price @ 10K: NA; Price @ 1K: NA; Vendor: NA; Vendor_Part_No: NA; eI Part#: NA
U4 = xc2c32a_vq44: IC CR-II CPLD 64MCELL 44-VQFP; Alt Mfg: Xilinx Inc; Alt Mfg Part#: XC2C64A-5VQG44C; Distributor_name: DIGIKEY; Distributor_part_number: XC2C64A-7VQG44C-ND; EIC Part#: TBD; Manufacture: Xilinx Inc; Manufacture(English): Xilinx Inc; Manufacturer: Xilinx Inc; Mfg: Xilinx Inc; Mfr_name: Xilinx Inc; Part #: 103919-0001R; Price @ 1K: 3.19200; Vendor: DIGIKEY; Vendor_Part_No: XC2C64A-7VQG44C-ND; eI Part#: TBD
U80 = MT48LC4M16A2B4: 1 Meg x 16 x 4 banks SDRAM; Distributor_name: Chip1Stop; EIC Part#: TBD; Manufacture: Micron; Manufacture(English): Micron; Manufacturer: Micron; Mfg: Micron; Mfgr: Micron; Mfr_name: Micron; Package: 54 VFBGA; Part #: 100969-0075R; RoHS: Yes; Vendor: Micron; eI Part#: TBD

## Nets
GND: C4.2 C105.2 C107.2 C108.1 C116.2 C175.1 C183.1 C411.1 C412.2 C427.2 C534.1 C958.2 C959.2 C960.2 C961.2 C962.2 C963.2 C964.2 EEPROM1.4(VSS) NAND1.C5(VSS1) NAND1.F7(NC_VSS1) NAND1.K3(VSS2) NAND1.K8(VSS3) R154.1 R226.1 R237.1 R512.1 R513.1 R522.2 R592.1 R621.1 R876.2 TP21.1 U4.4(GND1) U4.17(GND2) U4.25(GND3) U15.1(~{OE}) U15.3(GND) U64.4(GND) U80.A1(VSS1) U80.A3(VSSQ1) U80.B7(VSSQ2) U80.C3(VSSQ3) U80.D7(VSSQ4) U80.E3(VSS2) U80.J1(VSS3) ; also on sheet 1 2 3 4 5 6 8 10 11 12 13 14 15 16 17 18 19 20 21 22 24 25 26 27 28 29 33 34 35 36 37 40 43 45 46 47
VCC1V8: C105.1 C107.1 C108.2 C116.1 C183.2 C534.2 EEPROM1.8(VCC) NAND1.D3(NC_VCC1) NAND1.G4(NC_VCC2) NAND1.H8(VCCQ) NAND1.J6(VCC) R153.2 R229.2 R232.1 R233.2 R370.1 R375.1 R615.1 R618.1 U15.5(VCC) U64.1(VCCA) ; also on sheet 2 6 8 11 19 21 22 25 26 27 29 33 34 36 37
VCC3V3_MP: C175.2 R614.1 ; also on sheet 4 5 18 22 37
VDDCMON: U30.K10(VDDCMON) ; also on sheet 35
VSSCMON: U30.K9(VSSCMON) ; also on sheet 35
BMC_I2C1_SCL: U64.7(SCLB) ; also on sheet 4 5 40 45 47
BMC_I2C1_SDA: U64.6(SDAB) ; also on sheet 4 5 40 45 47
CPLD_A0: U4.2(IO12_8) U80.H7(A0) ; also on sheet 15
CPLD_A1: U4.3(IO2_9) U80.H8(A1) ; also on sheet 15
CPLD_A2: U4.5(IO12_10) U80.J8(A2) ; also on sheet 15
CPLD_A3: U4.6(IO12_11) U80.J7(A3) ; also on sheet 15
CPLD_BIO_0: U4.42(IO12_4) ; also on sheet 15
CPLD_BIO_1: U4.43(IO12_5) ; also on sheet 15
CPLD_BIO_2: U4.44(IO12_6) ; also on sheet 15
CPLD_BIO_3: R546.2 U4.1(IO12_7) ; also on sheet 15
CPLD_BIO_4: R549.2 U4.41(IO12_3) ; also on sheet 15
CPLD_CSn: U4.8(IO12_12) ; also on sheet 15
CPLD_D0: U4.39(IO12_1) U80.A8(DQ0) ; also on sheet 15
CPLD_D1: U4.40(IO12_2) U80.B9(DQ1) ; also on sheet 15
CPLD_RDn: U4.12(IO12_13) ; also on sheet 15
CPLD_RESETn: R512.2 U4.13(IO12_14) ; also on sheet 15
CPLD_RXD1: R549.1 ; also on sheet 10
CPLD_TCK: R522.1 TP9.1 U4.11(TCK) ; also on sheet 14
CPLD_TDI: TP17.1 U4.9(TDI) ; also on sheet 14
CPLD_TDO: TP8.1 U4.24(TDO) ; also on sheet 14
CPLD_TMS: R527.1 TP11.1 U4.10(TMS) ; also on sheet 14
CPLD_TXD1: R546.1 ; also on sheet 10
CPLD_WEn: U4.14(IO12_15) U80.F9(~{WE}) ; also on sheet 15
EEPROM_WPZ_FPGA_1V8_EXP3: EEPROM1.7(~{WC}) R232.2 ; also on sheet 28
EMIFA00: U30.W30(EMIFA00_GPIO32) ; also on sheet 21
EMIFA01: U30.R29(EMIFA01_GPIO33) ; also on sheet 21
EMIFA02: U30.R30(EMIFA02_GPIO34) ; also on sheet 21
EMIFA03: U30.P28(EMIFA03_GPIO35) ; also on sheet 21
EMIFA04: U30.P26(EMIFA04_GPIO36) ; also on sheet 21
EMIFA05: U30.R26(EMIFA05_GPIO37) ; also on sheet 21
EMIFA06: U30.V29(EMIFA06_GPIO38) ; also on sheet 21
EMIFA07: U30.AA30(EMIFA07_GPIO39) ; also on sheet 21
EMIFA08: U30.T29(EMIFA08_GPIO40) ; also on sheet 21
EMIFA09: U30.R28(EMIFA09_GPIO41) ; also on sheet 21
EMIFA10: U30.P27(EMIFA10_GPIO42) ; also on sheet 21
EMIFA11: NAND1.C4(ALE) U30.AD30(EMIFA11) ; also on sheet 21
EMIFA12: NAND1.D5(CLE) U30.V28(EMIFA12) ; also on sheet 21
EMIFA13: U30.Y29(EMIFA13_GPIO43) ; also on sheet 21
EMIFA14: U30.T28(EMIFA14_GPIO44) ; also on sheet 21
EMIFA15: U30.Y28(EMIFA15_GPIO45) ; also on sheet 21
EMIFA16: U30.T26(EMIFA16_GPIO46) ; also on sheet 21
EMIFA17: U30.T27(EMIFA17_GPIO47) ; also on sheet 21
EMIFA18: U30.R27(EMIFA18_UART2RTS) ; also on sheet 21
EMIFA19: U30.AC29(EMIFA19_UART2CTS) ; also on sheet 21
EMIFA20: U30.AB29(EMIFA20_UART2RXD) ; also on sheet 21
EMIFA21: U30.U27(EMIFA21_UART2TXD) ; also on sheet 21
EMIFA22: U30.W28(EMIFA22_UART3RXD) ; also on sheet 21
EMIFA23: U30.V27(EMIFA23_UART3TXD) ; also on sheet 21
EMIFBE0Z: U30.AB30(EMIFBE0Z) ; also on sheet 21
EMIFBE1Z: U30.P29(EMIFBE1Z) ; also on sheet 21
EMIFCE0Z: R368.1 U30.N30(EMIFCE0Z)
EMIFCE1Z: U30.U30(EMIFCE1Z) ; also on sheet 21
EMIFCE2Z: U30.W29(EMIFCE2Z_UART3RTS) ; also on sheet 21
EMIFCE3Z: U30.P30(EMIFCE3Z_UART3CTS) ; also on sheet 21
EMIFD0: NAND1.H4(IO0) U30.U26(EMIFD00) ; also on sheet 21
EMIFD1: NAND1.J4(IO1) U30.AB28(EMIFD01) ; also on sheet 21
EMIFD2: NAND1.K4(IO2) U30.W27(EMIFD02) ; also on sheet 21
EMIFD3: NAND1.K5(IO3) U30.AC28(EMIFD03) ; also on sheet 21
EMIFD4: NAND1.K6(IO4) U30.Y27(EMIFD04) ; also on sheet 21
EMIFD5: NAND1.J7(IO5) U30.AB27(EMIFD05) ; also on sheet 21
EMIFD6: NAND1.K7(IO6) U30.AA27(EMIFD06) ; also on sheet 21
EMIFD7: NAND1.J8(IO7) U30.V26(EMIFD07) ; also on sheet 21
EMIFD8: U30.AD27(EMIFD08) ; also on sheet 21
EMIFD9: U30.AC27(EMIFD09) ; also on sheet 21
EMIFD10: U30.W26(EMIFD10) ; also on sheet 21
EMIFD11: U30.AD26(EMIFD11) ; also on sheet 21
EMIFD12: U30.AC26(EMIFD12) ; also on sheet 21
EMIFD13: U30.AA26(EMIFD13) ; also on sheet 21
EMIFD14: U30.Y26(EMIFD14) ; also on sheet 21
EMIFD15: U30.AB26(EMIFD15) ; also on sheet 21
EMIFOEZ: NAND1.D4(RE#) U30.T30(EMIFOEZ) ; also on sheet 21
EMIFRNW: U30.M30(EMIFRNW) ; also on sheet 21
EMIFWAIT0: NAND1.C8(R/B#) R370.2 U30.Y30(EMIFWAIT0)
EMIFWAIT1: R375.2 U15.4(Y) U30.AC30(EMIFWAIT1)
EMIFWEZ: NAND1.C7(WE#) U30.V30(EMIFWEZ) ; also on sheet 21
MEM_A4: U80.J3(A4) ; also on sheet 15
MEM_A5: U80.J2(A5) ; also on sheet 15
MEM_A6: U80.H3(A6) ; also on sheet 15
MEM_A7: U80.H2(A7) ; also on sheet 15
MEM_A8: U80.H1(A8) ; also on sheet 15
MEM_A9: U80.G3(A9) ; also on sheet 15
MEM_A10: U80.H9(A10) ; also on sheet 15
MEM_A11: U80.G2(A11) ; also on sheet 15
MEM_BA0: U80.G7(BA0) ; also on sheet 15
MEM_BA1: U80.G8(BA1) ; also on sheet 15
MEM_CASn: U80.F7(~{CAS}) ; also on sheet 15
MEM_CKE: U80.F3(CKE) ; also on sheet 15
MEM_CLK: U80.F2(CLK) ; also on sheet 15
MEM_CS0n: U80.G9(~{CS}) ; also on sheet 15
MEM_D2: U80.B8(DQ2) ; also on sheet 15
MEM_D3: U80.C9(DQ3) ; also on sheet 15
MEM_D4: U80.C8(DQ4) ; also on sheet 15
MEM_D5: U80.D9(DQ5) ; also on sheet 15
MEM_D6: U80.D8(DQ6) ; also on sheet 15
MEM_D7: U80.E9(DQ7) ; also on sheet 15
MEM_D8: U80.E1(DQ8) ; also on sheet 15
MEM_D9: U80.D2(DQ9) ; also on sheet 15
MEM_D10: U80.D1(DQ10) ; also on sheet 15
MEM_D11: U80.C2(DQ11) ; also on sheet 15
MEM_D12: U80.C1(DQ12) ; also on sheet 15
MEM_D13: U80.B2(DQ13) ; also on sheet 15
MEM_D14: U80.B1(DQ14) ; also on sheet 15
MEM_D15: U80.A2(DQ15) ; also on sheet 15
MEM_RASn: U80.F8(~{RAS}) ; also on sheet 15
MEM_WE_DQM0n: U80.E8(DQML) ; also on sheet 15
MEM_WE_DQM1n: U80.F1(DQMH) ; also on sheet 15
NAND_WPZ_FPGA_1V8_EXP3: NAND1.C3(WP#) R592.2 ; also on sheet 28
SOC_EMIFCE0Z: NAND1.C6(CE#) R368.2
SOC_EMIFWAIT1: U15.2(A) ; also on sheet 26
SOC_I2C0_SCL: EEPROM1.6(SCL) R615.2 U64.2(SCLA) ; also on sheet 29
SOC_I2C0_SDA: EEPROM1.5(SDA) R618.2 U64.3(SDAA) ; also on sheet 29
SOC_I2C_EN: R621.2 U64.5(EN) ; also on sheet 5
SPARE0: TP1.1 U4.20(IO21_15)
SPARE1: TP2.1 U4.19(IO21_16)
T_TDIS: R1.2 R2.2 TP3.1
TRGRSTZ: R46.2 ; also on sheet 6 22
uEMU0: R57.1 U4.33(IO21_5)
uEMU1: R52.1 U4.32(IO21_6)
uEXP0: R542.1 U4.29(IO21_9)
uEXP1: R538.1 U4.28(IO21_10)
uEXP2: R536.1 U4.27(IO21_11)
uEXP3: R517.1 U4.23(IO21_12)
uRTCK: R515.1 U4.22(IO21_13)
uSRSTn: R46.1 U4.31(IO21_7)
uTCK: R65.1 U4.34(IO21_4)
uTDI: R550.1 U4.38(IO21_1)
uTDIS: R2.1 R876.1 U4.18(I_2)
uTDO: R514.1 U4.21(IO21_14)
uTMS: R551.1 U4.37(IO21_2)
uTMSK: R36.1 U4.30(IO21_8)
uTRSTn: R552.1 U4.36(IO21_3)
XDS200_EMU0: R57.2 ; also on sheet 6
XDS200_EMU1: R52.2 ; also on sheet 6
XDS200_TCK: R65.2 ; also on sheet 6
XDS200_TDI: R550.2 ; also on sheet 6
XDS200_TDO: R514.2 ; also on sheet 6
XDS200_TMS: R36.2 R551.2 ; also on sheet 6
XDS200_TRST#: R552.2 ; also on sheet 6
XDS_1V8: C4.1 R521.2 U4.15(VCC18) ; also on sheet 10 15 24
XDS_RTCK: R515.2 ; also on sheet 6
XDS_VCC3V3: C411.2 C412.1 C427.1 C958.1 C959.1 C960.1 C961.1 C962.1 C963.1 C964.1 R1.1 R526.2 R527.2 TP15.1 U4.7(VCCIO1) U4.35(VCCAUX) U80.A7(VDDQ1) U80.A9(VDD1) U80.B3(VDDQ2) U80.C7(VDDQ3) U80.D3(VDDQ4) U80.E7(VDD2) U80.J9(VDD3) ; also on sheet 10 14 15 24
N17841181: EEPROM1.2(E1) R233.1 R237.2
N17841191: EEPROM1.3(E2) R226.2 R229.1
N17842782: R614.2 U64.8(VCCB)
N17845225: NAND1.G5(LOCKPRE/DNU) R153.1 R154.2
N18207828: R521.1 R526.1 U4.26(VCCIO2)
N18208333: R536.2 TP10.1
N18208340: R517.2 TP6.1
N18208342: R542.2 TP18.1
N18208349: R538.2 TP16.1
N18512558: R513.2 U4.16(IO12)
N19579138: R371.1 U30.N23(VDDTMON)
N21067964: R371.2 TP78.1
N21067966: R369.1 U30.M23(VSSTMON)
N21067968: R369.2 TP76.1

Not connected (* = marked no-connect by the designer): EEPROM1 1(DU)*; NAND1 A1(NC1)* A2(NC2)* A9(NC3)* A10(NC4)* B1(NC5)* B9(NC6)* B10(NC7)* D6(NC16)* D7(NC17)* D8(NC18)* E3(NC19)* E4(NC20)* E5(NC21)* E6(NC22)* E7(NC23)* E8(NC24)* F3(NC25)* F4(NC26)* F5(NC27)* F6(NC28)* F8(NC29)* G3(DNU)* G6(NC/IO13)* G7(NC/IO15)* G8(NC32)* H3(NC/IO8)* H5(NC/IO10)* H6(NC/IO12)* H7(NC/IO14)* J3(NC/IO9)* J5(NC/IO11)* L1(NC8)* L2(NC9)* L9(NC10)* L10(NC11)* M1(NC12)* M2(NC13)* M9(NC14)* M10(NC15)*; U80 E2(NC1)* G1(NC2)*

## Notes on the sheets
sheet 41
- K2L EMIF, VDD and VSSMON, EMIFWAIT1 bfr, NAND Flash, I2C EEPROM
- NAND FLASH
- K2L EMIF
- Note: VCCMON group and EMIF group are different
  as per IO sheet 0.7
- EMIFWAIT1 bfr
- Note: NAND FLASH Device size is 2GB.
- 1M-bit I2C EEPROM
- 0x50h/0x51h
- SOC to BMC
  I2C bridge
sheet 42
- XDS200 Emulation CPLD
- REV-B
- CLAMP TVD TO 4.3v (VCC_5V-.7) AND BLOCK
  TVD WHEN USB IS NOT POWERED.
